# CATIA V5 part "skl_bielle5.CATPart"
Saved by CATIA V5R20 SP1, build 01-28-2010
Part number: skl_bielle5
Publications: "Droite.1", "Droite.2", "Droite.3", "Plan xy"
Bounding box of the stored display mesh (mm): x 0 to 161.915, y 0 to 1128.443, z -100 to 100
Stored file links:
  C:\Users\Manon\Desktop\IAO\SKL_rlanglais\skl_bielle5.CATPart
  C:\Users\Manon\Desktop\IAO\SKL_rlanglais\SKL_rlanglais.CATProduct
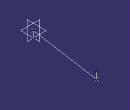
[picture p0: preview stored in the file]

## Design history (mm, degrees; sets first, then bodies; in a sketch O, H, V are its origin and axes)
Set1
  Point1 "F": linked copy from another document
  Point2 "G": linked copy from another document
Set2
  Line1: type PtPt, FirstPoint Point1, SecondPoint Point2
  Line2: type Normal, RefPoint Point2, RefSkin xy-plane, Start 0, End 100
  Line3: type Normal, RefPoint Point1, RefSkin xy-plane, Start 0, End 100
Body1 (main body)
